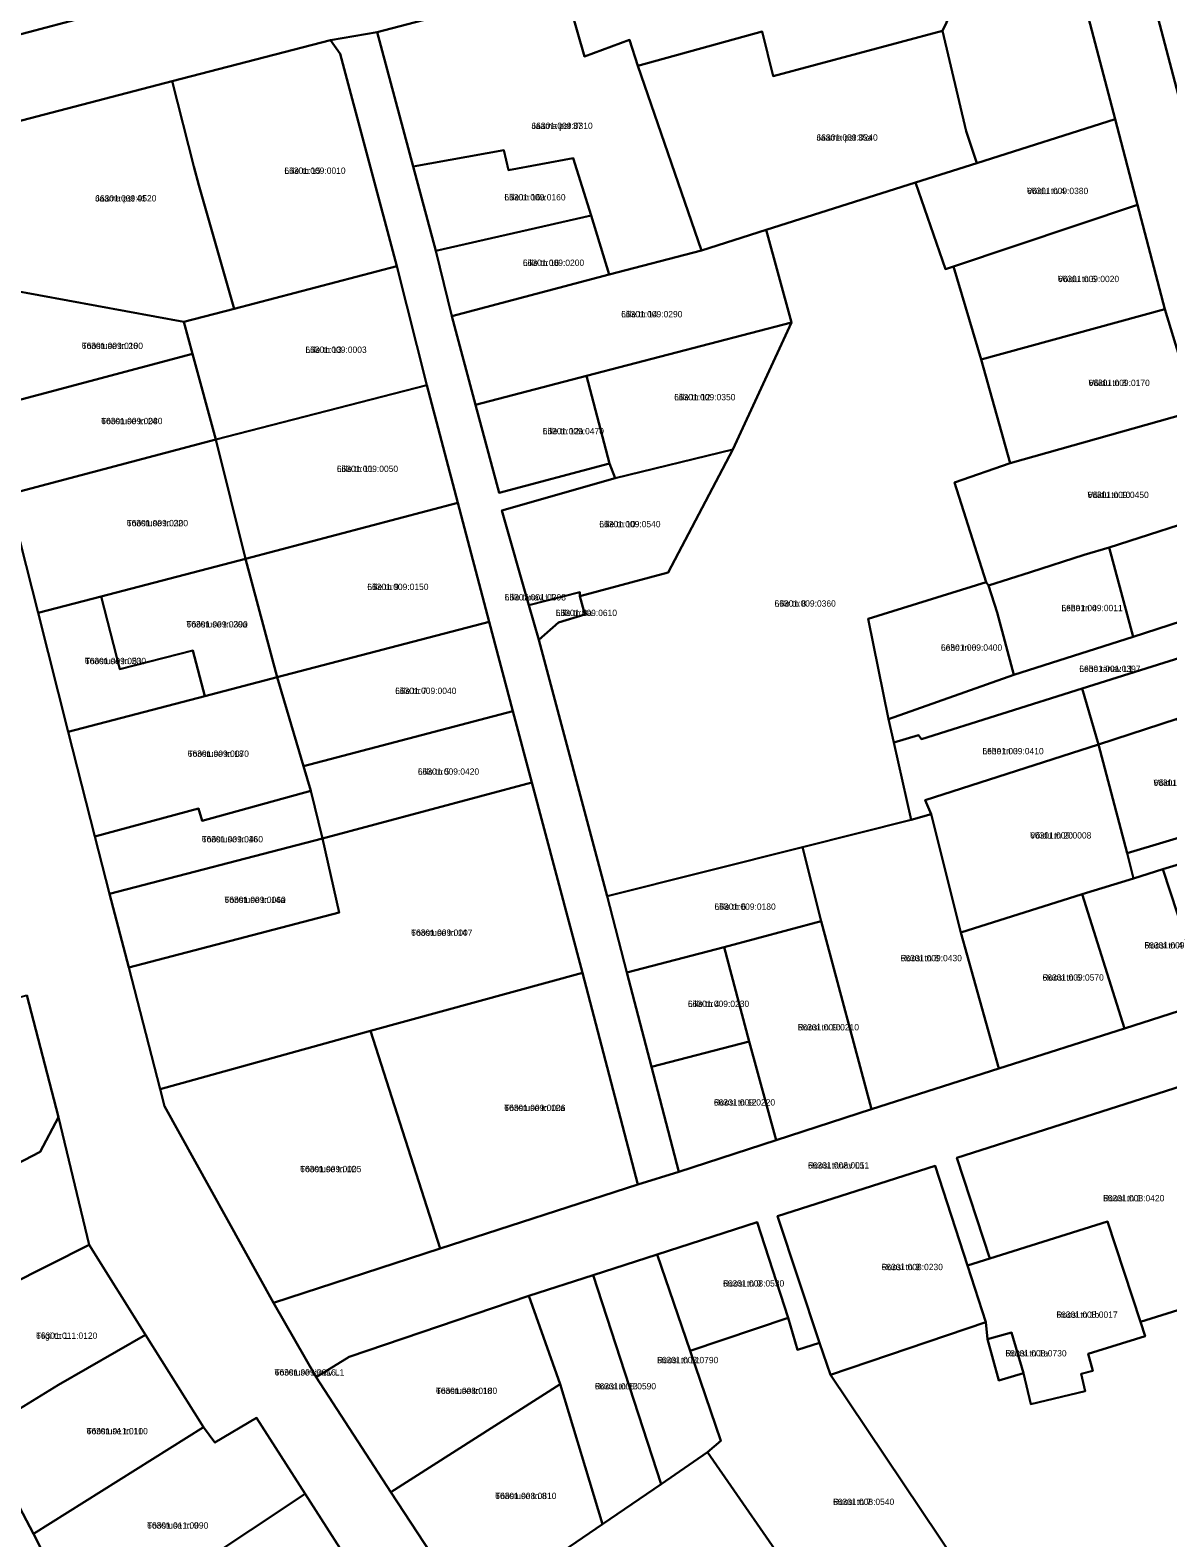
# Model space of a CAD drawing. Extents: x 632278 to 636344, y 6578401 to 6583362.
# Drawn here: x 633950.5 to 634219.9, y 6581799.1 to 6582156.3 of the extents above; entities that cross this region are included whole.
import ezdxf

# ---------------------------------------------------------------- set-up
doc = ezdxf.new("R2010")
doc.units = 0
for name, color, linetype in [('L_AADRESS', 7, 'Continuous'), ('PIIR', 7, 'Continuous'), ('TUNNUS', 7, 'Continuous')]:
    doc.layers.add(name, color=color, linetype=linetype)

msp = doc.modelspace()

# ---------------------------------------------------------------- linework, layer by layer
at = {"layer": 'PIIR'}
for points in [[(634226.55, 6582066.12), (634219.18, 6582090.2), (634212.69, 6582114.9), (634207.44, 6582135.18), (634193.9, 6582186.62), (634190.63, 6582199.04), (634184.13, 6582216.44), (634176.42, 6582237.01), (634195.12, 6582241.6), (634202.12, 6582218.6), (634206.36, 6582202), (634232.85, 6582101.14)], [(633468.65, 6582027.37), (633862.14, 6582132.61), (633966.83, 6582160.24), (634045.32, 6582180.97), (634095.76, 6582194.28), (634171.8, 6582213.35), (634184.13, 6582216.44), (634190.63, 6582199.04), (634142.64, 6582185.7), (634076.76, 6582167.38), (634032.67, 6582155.81), (634021.59, 6582153.91), (633984.06, 6582144.17), (633935.96, 6582131.59), (633888.34, 6582118.77), (633834.04, 6582103.56), (633748.13, 6582082.98), (633734.4, 6582070.6), (633580.94, 6582031.55)], [(633945.26, 6582046.29), (633952.38, 6582018.2), (633959.5, 6581990.06), (633965.77, 6581965.26), (633969.26, 6581951.67), (633973.83, 6581934.24), (633981.27, 6581905.36), (633982.32, 6581901.36), (634008.06, 6581854.81), (634018.24, 6581837.15), (634035.92, 6581809.94), (634054.81, 6581781.02)], [(634028.93, 6581788.71), (634015.57, 6581809.57), (634004.07, 6581827.51), (633994.24, 6581821.7), (633991.52, 6581825.32), (633989.41, 6581828.7), (633977.8, 6581847.2), (633964.41, 6581868.52), (633957.19, 6581898.78), (633949.71, 6581927.69)], [(634227.03, 6581907.36), (634169.9, 6581889.15), (634177.71, 6581865.32), (634172.48, 6581863.61), (634164.82, 6581887.26), (634127.43, 6581875.31), (634137.41, 6581845.3), (634132.2, 6581843.65), (634129.96, 6581851.23), (634122.65, 6581873.89), (634098.97, 6581866.23), (634083.84, 6581861.37), (634068.54, 6581856.46), (634026, 6581842.02), (634018.24, 6581837.15), (634008.06, 6581854.81), (634047.55, 6581867.62), (634094.4, 6581882.82), (634104.1, 6581885.8), (634127.15, 6581893.28), (634149.71, 6581900.62), (634179.88, 6581910.28), (634209.63, 6581919.77), (634229.1, 6581926.04)], [(634221.83, 6581772.31), (634198.51, 6581756.88), (634177.24, 6581788.29), (634174.47, 6581786.38), (634139.98, 6581837.74), (634176.83, 6581850.19), (634177.17, 6581846.17), (634179.86, 6581836.37), (634185.69, 6581838.09), (634187.47, 6581830.76), (634200.35, 6581833.87), (634199.37, 6581837.93), (634202.14, 6581838.66), (634201.07, 6581842.72), (634214.55, 6581846.87), (634213.43, 6581850.29), (634242.25, 6581859.26)]]:
    msp.add_lwpolyline(points, dxfattribs=at)
for points in [[(634206.36, 6582202), (634226.54, 6582207.17), (634227.13, 6582204.73), (634230.32, 6582192.25), (634233.16, 6582187.01), (634241.86, 6582153.04), (634252.38, 6582112.67), (634246.39, 6582104.55), (634232.85, 6582101.14)], [(634092.4, 6582154), (634081.72, 6582150.06), (634076.76, 6582167.38), (634142.64, 6582185.7), (634147.97, 6582167.04), (634164.74, 6582171.61), (634166.49, 6582164.58), (634171.19, 6582165.88), (634166.54, 6582156.12), (634126.47, 6582145.38), (634123.83, 6582155.98), (634094.42, 6582147.84)], [(634172.12, 6582132.37), (634166.54, 6582156.12), (634171.19, 6582165.88), (634178.5, 6582181.21), (634193.9, 6582186.62), (634207.44, 6582135.18), (634174.63, 6582124.76)], [(633961.3, 6582182.01), (633966.83, 6582160.24), (633862.14, 6582132.61), (633857.97, 6582155.11)], [(634062.61, 6582127.87), (634041.15, 6582123.97), (634032.67, 6582155.81), (634076.76, 6582167.38), (634081.72, 6582150.06), (634092.4, 6582154), (634094.42, 6582147.84), (634109.47, 6582104.07), (634087.56, 6582098.35), (634083.36, 6582112.35), (634079.03, 6582125.95), (634063.73, 6582123.14)], [(634160.12, 6582120.16), (634124.79, 6582108.93), (634109.47, 6582104.07), (634094.42, 6582147.84), (634123.83, 6582155.98), (634126.47, 6582145.38), (634166.54, 6582156.12), (634172.12, 6582132.37), (634174.63, 6582124.76)], [(633989.26, 6582123.94), (633984.06, 6582144.17), (634021.59, 6582153.91), (634023.89, 6582150.67), (634037.28, 6582100.34), (633998.8, 6582090.29), (633990.45, 6582119.57)], [(634023.89, 6582150.67), (634021.59, 6582153.91), (634032.67, 6582155.81), (634041.15, 6582123.97), (634046.52, 6582103.99), (634050.35, 6582088.48), (634055.94, 6582067.54), (634061.58, 6582046.69), (634087.71, 6582053.63), (634088.99, 6582050.13), (634062.17, 6582042.45), (634068.6, 6582020.08), (634070.94, 6582011.82), (634087.12, 6581951.1), (634091.78, 6581933.02), (634097.64, 6581910.69), (634104.1, 6581885.8), (634094.4, 6581882.82), (634081.28, 6581932.96), (634069.28, 6581978.08), (634064.77, 6581994.97), (634059.16, 6582016.14), (634051.79, 6582044.29), (634044.4, 6582072.2), (634037.28, 6582100.34)], [(633984.06, 6582144.17), (633989.26, 6582123.94), (633990.45, 6582119.57), (633998.8, 6582090.29), (633986.84, 6582087.18), (633945.69, 6582094.79), (633935.96, 6582131.59)], [(634167.23, 6582099.67), (634160.12, 6582120.16), (634174.63, 6582124.76), (634207.44, 6582135.18), (634212.69, 6582114.9), (634169.12, 6582100.29)], [(634046.52, 6582103.99), (634041.15, 6582123.97), (634062.61, 6582127.87), (634063.73, 6582123.14), (634079.03, 6582125.95), (634083.36, 6582112.35)], [(634087.12, 6581951.1), (634070.94, 6582011.82), (634075.62, 6582015.91), (634081.85, 6582017.88), (634080.67, 6582022.2), (634101.59, 6582027.77), (634116.86, 6582056.94), (634130.8, 6582087.03), (634124.79, 6582108.93), (634160.12, 6582120.16), (634167.23, 6582099.67), (634169.12, 6582100.29), (634175.72, 6582078.27), (634182.6, 6582053.72), (634169.36, 6582049.12), (634176.87, 6582025.47), (634148.91, 6582016.78), (634153.75, 6581993.05), (634154.99, 6581987.54), (634159.1, 6581969.18), (634133.38, 6581962.74)], [(634169.12, 6582100.29), (634212.69, 6582114.9), (634219.18, 6582090.2), (634175.72, 6582078.27)], [(634046.52, 6582103.99), (634083.36, 6582112.35), (634087.56, 6582098.35), (634050.35, 6582088.48)], [(634055.94, 6582067.54), (634050.35, 6582088.48), (634087.56, 6582098.35), (634109.47, 6582104.07), (634124.79, 6582108.93), (634130.8, 6582087.03), (634082.19, 6582074.37)], [(633986.84, 6582087.18), (633998.8, 6582090.29), (634037.28, 6582100.34), (634044.4, 6582072.2), (633994.43, 6582059.31), (633988.91, 6582079.57)], [(633934.01, 6582091.91), (633945.69, 6582094.79), (633986.84, 6582087.18), (633988.91, 6582079.57), (633940.23, 6582066.68)], [(634226.55, 6582066.12), (634182.6, 6582053.72), (634175.72, 6582078.27), (634219.18, 6582090.2)], [(634130.8, 6582087.03), (634116.86, 6582056.94), (634088.99, 6582050.13), (634087.71, 6582053.63), (634082.19, 6582074.37)], [(633945.26, 6582046.29), (633940.23, 6582066.68), (633988.91, 6582079.57), (633994.43, 6582059.31)], [(634055.94, 6582067.54), (634082.19, 6582074.37), (634087.71, 6582053.63), (634061.58, 6582046.69)], [(634044.4, 6582072.2), (634051.79, 6582044.29), (634001.45, 6582031.02), (633994.43, 6582059.31)], [(634187.38, 6582027.9), (634177.46, 6582024.73), (634176.87, 6582025.47), (634169.36, 6582049.12), (634182.6, 6582053.72), (634226.55, 6582066.12), (634231.98, 6582042.08), (634206, 6582033.74), (634200.11, 6582031.95)], [(633952.38, 6582018.2), (633945.26, 6582046.29), (633994.43, 6582059.31), (634001.45, 6582031.02), (633967.32, 6582022.1)], [(634080.63, 6582023.12), (634068.6, 6582020.08), (634062.17, 6582042.45), (634088.99, 6582050.13), (634116.86, 6582056.94), (634101.59, 6582027.77), (634080.67, 6582022.2)], [(634001.45, 6582031.02), (634051.79, 6582044.29), (634059.16, 6582016.14), (634008.94, 6582002.98)], [(634206, 6582033.74), (634231.98, 6582042.08), (634237.47, 6582020.95), (634211.69, 6582012.56)], [(634206, 6582033.74), (634211.69, 6582012.56), (634183.42, 6582003.53), (634179.48, 6582018.29), (634177.46, 6582024.73), (634187.38, 6582027.9), (634200.11, 6582031.95)], [(633988.99, 6582009.3), (633971.7, 6582004.89), (633967.32, 6582022.1), (634001.45, 6582031.02), (634008.94, 6582002.98), (633991.82, 6581998.51)], [(634148.91, 6582016.78), (634176.87, 6582025.47), (634177.46, 6582024.73), (634179.48, 6582018.29), (634183.42, 6582003.53), (634153.75, 6581993.05)], [(633952.38, 6582018.2), (633967.32, 6582022.1), (633971.7, 6582004.89), (633988.99, 6582009.3), (633991.82, 6581998.51), (633959.5, 6581990.06)], [(634068.6, 6582020.08), (634080.63, 6582023.12), (634080.67, 6582022.2), (634081.85, 6582017.88), (634075.62, 6582015.91), (634070.94, 6582011.82)], [(634153.75, 6581993.05), (634183.42, 6582003.53), (634211.69, 6582012.56), (634237.47, 6582020.95), (634239.59, 6582012.85), (634199.6, 6582000.28), (634161.6, 6581988.33), (634160.85, 6581989.22), (634154.99, 6581987.54)], [(634015.2, 6581981.9), (634008.94, 6582002.98), (634059.16, 6582016.14), (634064.77, 6581994.97)], [(634199.6, 6582000.28), (634239.59, 6582012.85), (634243.14, 6581999.8), (634222.13, 6581993.15), (634203.45, 6581987.01)], [(633959.5, 6581990.06), (633991.82, 6581998.51), (634008.94, 6582002.98), (634015.2, 6581981.9), (634016.95, 6581976.03), (633991.18, 6581968.96), (633990.31, 6581971.87), (633965.77, 6581965.26)], [(634163.82, 6581970.51), (634159.1, 6581969.18), (634154.99, 6581987.54), (634160.85, 6581989.22), (634161.6, 6581988.33), (634199.6, 6582000.28), (634203.45, 6581987.01), (634162.44, 6581973.83)], [(634016.95, 6581976.03), (634015.2, 6581981.9), (634064.77, 6581994.97), (634069.28, 6581978.08), (634019.67, 6581964.78)], [(634203.45, 6581987.01), (634222.13, 6581993.15), (634229.57, 6581967.08), (634210.24, 6581961.3)], [(634203.45, 6581987.01), (634210.24, 6581961.3), (634211.79, 6581955.34), (634199.64, 6581951.59), (634170.85, 6581942.52), (634163.82, 6581970.51), (634162.44, 6581973.83)], [(633973.83, 6581934.24), (634023.64, 6581947.26), (634019.67, 6581964.78), (634069.28, 6581978.08), (634081.28, 6581932.96), (634031.1, 6581919.25), (633981.27, 6581905.36)], [(633965.77, 6581965.26), (633990.31, 6581971.87), (633991.18, 6581968.96), (634016.95, 6581976.03), (634019.67, 6581964.78), (633969.26, 6581951.67)], [(634137.82, 6581945.16), (634133.38, 6581962.74), (634159.1, 6581969.18), (634163.82, 6581970.51), (634170.85, 6581942.52), (634179.88, 6581910.28), (634149.71, 6581900.62)], [(634210.24, 6581961.3), (634229.57, 6581967.08), (634250.38, 6581973.11), (634251.88, 6581967.45), (634218.71, 6581957.48), (634211.79, 6581955.34)], [(634229.1, 6581926.04), (634218.71, 6581957.48), (634251.88, 6581967.45), (634260.19, 6581936.06)], [(634019.67, 6581964.78), (634023.64, 6581947.26), (633973.83, 6581934.24), (633969.26, 6581951.67)], [(634137.82, 6581945.16), (634114.81, 6581939.04), (634091.78, 6581933.02), (634087.12, 6581951.1), (634133.38, 6581962.74)], [(634199.64, 6581951.59), (634211.79, 6581955.34), (634218.71, 6581957.48), (634229.1, 6581926.04), (634209.63, 6581919.77)], [(634170.85, 6581942.52), (634199.64, 6581951.59), (634209.63, 6581919.77), (634179.88, 6581910.28)], [(634120.74, 6581916.72), (634114.81, 6581939.04), (634137.82, 6581945.16), (634149.71, 6581900.62), (634127.15, 6581893.28)], [(634091.78, 6581933.02), (634114.81, 6581939.04), (634120.74, 6581916.72), (634097.64, 6581910.69)], [(634031.1, 6581919.25), (634081.28, 6581932.96), (634094.4, 6581882.82), (634047.55, 6581867.62)], [(633949.71, 6581927.69), (633957.19, 6581898.78), (633952.86, 6581890.56), (633928.96, 6581878.19), (633909.81, 6581916.52)], [(634031.1, 6581919.25), (634047.55, 6581867.62), (634008.06, 6581854.81), (633982.32, 6581901.36), (633981.27, 6581905.36)], [(634097.64, 6581910.69), (634120.74, 6581916.72), (634127.15, 6581893.28), (634104.1, 6581885.8)], [(634205.6, 6581874.01), (634177.71, 6581865.32), (634169.9, 6581889.15), (634227.03, 6581907.36), (634235.96, 6581878.51), (634242.25, 6581859.26), (634213.43, 6581850.29)], [(633746.05, 6581778.31), (633776.36, 6581792.95), (633778.15, 6581801.53), (633782.1, 6581812.81), (633788.02, 6581811.01), (633819.19, 6581824.49), (633851.9, 6581840.4), (633879.17, 6581853.47), (633905.37, 6581866.61), (633928.96, 6581878.19), (633952.86, 6581890.56), (633957.19, 6581898.78), (633964.41, 6581868.52), (633926.12, 6581849.23), (633822.63, 6581796.54), (633804.8, 6581787.45), (633771.82, 6581771.23), (633752.6, 6581762.41), (633751.15, 6581759.6)], [(634164.82, 6581887.26), (634172.48, 6581863.61), (634176.83, 6581850.19), (634139.98, 6581837.74), (634137.41, 6581845.3), (634127.43, 6581875.31)], [(634177.71, 6581865.32), (634205.6, 6581874.01), (634213.43, 6581850.29), (634214.55, 6581846.87), (634201.07, 6581842.72), (634202.14, 6581838.66), (634199.37, 6581837.93), (634200.35, 6581833.87), (634187.47, 6581830.76), (634185.69, 6581838.09), (634182.86, 6581847.72), (634177.17, 6581846.17), (634176.83, 6581850.19), (634172.48, 6581863.61)], [(634122.65, 6581873.89), (634129.96, 6581851.23), (634106.74, 6581843.39), (634098.97, 6581866.23)], [(633926.12, 6581849.23), (633964.41, 6581868.52), (633977.8, 6581847.2), (633957.17, 6581835.32), (633938.65, 6581823.98)], [(634098.97, 6581866.23), (634106.74, 6581843.39), (634114.03, 6581822.11), (634110.85, 6581819.43), (634099.87, 6581811.86), (634083.84, 6581861.37)], [(634076.01, 6581835.55), (634068.54, 6581856.46), (634083.84, 6581861.37), (634099.87, 6581811.86), (634086, 6581802.32)], [(634035.92, 6581809.94), (634018.24, 6581837.15), (634026, 6581842.02), (634068.54, 6581856.46), (634076.01, 6581835.55)], [(633822.63, 6581796.54), (633926.12, 6581849.23), (633938.65, 6581823.98), (633951.22, 6581800.08), (633963.84, 6581775.08), (633962.93, 6581774.45), (633946.33, 6581763.28), (633949.27, 6581756.32), (633921.58, 6581741.86), (633930.19, 6581700.67), (633902.7, 6581686.51)], [(634110.85, 6581819.43), (634114.03, 6581822.11), (634106.74, 6581843.39), (634129.96, 6581851.23), (634132.2, 6581843.65), (634137.41, 6581845.3), (634139.98, 6581837.74), (634174.47, 6581786.38), (634147.62, 6581767.25), (634133.47, 6581786.87), (634132.44, 6581788.31)], [(633989.41, 6581828.7), (633991.52, 6581825.32), (633951.22, 6581800.08), (633938.65, 6581823.98), (633957.17, 6581835.32), (633977.8, 6581847.2)], [(634182.86, 6581847.72), (634185.69, 6581838.09), (634179.86, 6581836.37), (634177.17, 6581846.17)], [(634035.92, 6581809.94), (634076.01, 6581835.55), (634086, 6581802.32), (634054.81, 6581781.02)], [(633951.22, 6581800.08), (633991.52, 6581825.32), (633994.24, 6581821.7), (634004.07, 6581827.51), (634015.57, 6581809.57), (633963.84, 6581775.08)], [(634076.7, 6581746), (634054.81, 6581781.02), (634086, 6581802.32), (634099.87, 6581811.86), (634110.85, 6581819.43), (634132.44, 6581788.31), (634104.62, 6581766.7)], [(633977.33, 6581753.35), (633962.93, 6581774.45), (633963.84, 6581775.08), (634015.57, 6581809.57), (634028.93, 6581788.71), (633995.89, 6581766.18)]]:
    msp.add_lwpolyline(points, close=True, dxfattribs=at)

# ---------------------------------------------------------------- texts
at = {"layer": 'L_AADRESS'}
for s, p in [('Jaama pst 37', (634069.18, 6582132.87)), ('Jaama pst 35a', (634136.7, 6582130.1)), ('Lille tn 15', (634010.67, 6582122.23)), ('Jaama pst 41', (633965.86, 6582115.68)), ('Lille tn 16a', (634062.77, 6582115.93)), ('Võidu tn 4', (634186.55, 6582117.43)), ('Lille tn 16', (634067.17, 6582100.42)), ('Võidu tn 6', (634193.87, 6582096.58)), ('Lille tn 14', (634090.44, 6582088.24)), ('Tööstuse tn 26', (633962.68, 6582080.74)), ('Lille tn 13', (634015.66, 6582079.82)), ('Võidu tn 8', (634201.13, 6582071.96)), ('Lille tn 12', (634102.99, 6582068.58)), ('Tööstuse tn 24', (633967.3, 6582062.93)), ('Lille tn 12a', (634071.85, 6582060.53)), ('Lille tn 11', (634023.1, 6582051.61)), ('Võidu tn 10', (634200.88, 6582045.43)), ('Tööstuse tn 22', (633973.35, 6582038.75)), ('Lille tn 10', (634085.26, 6582038.51)), ('Lille tn 9', (634030.31, 6582023.63)), ('Lille tänav L1', (634062.85, 6582021.17)), ('Lille tn 8', (634126.77, 6582019.7)), ('Lille tn 8a', (634074.95, 6582017.47)), ('Lehe tn 4', (634194.71, 6582018.63)), ('Tööstuse tn 20a', (633987.49, 6582014.77)), ('Lehe tn 6', (634166.17, 6582009.26)), ('Tööstuse tn 20', (633963.42, 6582006.08)), ('Lehe tänav L1', (634198.94, 6582004.24)), ('Lille tn 7', (634036.91, 6581999.02)), ('Tööstuse tn 18', (633987.77, 6581984.12)), ('Lehe tn 3', (634175.99, 6581984.73)), ('Lille tn 5', (634042.3, 6581979.88)), ('Võidu tn 18', (634216.51, 6581977.24)), ('Tööstuse tn 16', (633991.11, 6581963.85)), ('Võidu tn 20', (634187.29, 6581964.77)), ('Tööstuse tn 14a', (633996.48, 6581949.51)), ('Lille tn 6', (634112.54, 6581947.88)), ('Tööstuse tn 14', (634040.7, 6581941.72)), ('Roosi tn 4', (634214.37, 6581938.72)), ('Roosi tn 8', (634156.63, 6581935.7)), ('Roosi tn 6', (634190.24, 6581931.11)), ('Lille tn 4', (634106.25, 6581924.87)), ('Roosi tn 10', (634132.26, 6581919.31)), ('Roosi tn 12', (634112.39, 6581901.52)), ('Tööstuse tn 12a', (634062.75, 6581900.22)), ('Tööstuse tn 12', (634014.41, 6581885.73)), ('Roosi tänav L1', (634134.68, 6581886.6)), ('Roosi tn 1', (634204.57, 6581878.82)), ('Roosi tn 3', (634152.13, 6581862.52)), ('Roosi tn 9', (634114.56, 6581858.64)), ('Roosi tn 1b', (634193.51, 6581851.23)), ('Tiigi tn 1', (633951.87, 6581846.25)), ('Roosi tn 11', (634098.94, 6581840.48)), ('Roosi tn 1a', (634181.43, 6581842.08)), ('Tööstuse tänav L1', (634008.36, 6581837.56)), ('Tööstuse tn 10', (634046.57, 6581833.2)), ('Roosi tn 13', (634084.2, 6581834.27)), ('Tööstuse tn 11', (633963.83, 6581823.64)), ('Tööstuse tn 8', (634060.6, 6581808.29)), ('Roosi tn 7', (634140.61, 6581806.89)), ('Tööstuse tn 9', (633978.16, 6581801.29))]:
    msp.add_text(s, height=1.5, dxfattribs=at).set_placement(p)
at = {"layer": 'TUNNUS'}
for s, p in [('66301:009:0310', (634069.18, 6582132.87)), ('66301:009:0240', (634136.7, 6582130.1)), ('66301:009:0010', (634010.67, 6582122.23)), ('66301:009:0520', (633965.86, 6582115.68)), ('66301:009:0160', (634062.77, 6582115.93)), ('66301:009:0380', (634186.55, 6582117.43)), ('66301:009:0200', (634067.17, 6582100.42)), ('66301:009:0020', (634193.87, 6582096.58)), ('66301:009:0290', (634090.44, 6582088.24)), ('66301:009:0100', (633962.68, 6582080.74)), ('66301:009:0003', (634015.66, 6582079.82)), ('66301:009:0170', (634201.13, 6582071.96)), ('66301:009:0350', (634102.99, 6582068.58)), ('66301:009:0080', (633967.3, 6582062.93)), ('66301:009:0470', (634071.85, 6582060.53)), ('66301:009:0050', (634023.1, 6582051.61)), ('66301:009:0450', (634200.88, 6582045.43)), ('66301:009:0300', (633973.35, 6582038.75)), ('66301:009:0540', (634085.26, 6582038.51)), ('66301:009:0150', (634030.31, 6582023.63)), ('66301:001:0398', (634062.85, 6582021.17)), ('66301:009:0360', (634126.77, 6582019.7)), ('66301:009:0610', (634074.95, 6582017.47)), ('66301:009:0011', (634194.71, 6582018.63)), ('66301:009:0390', (633987.49, 6582014.77)), ('66301:009:0400', (634166.17, 6582009.26)), ('66301:009:0530', (633963.42, 6582006.08)), ('66301:001:0397', (634198.94, 6582004.24)), ('66301:009:0040', (634036.91, 6581999.02)), ('66301:009:0070', (633987.77, 6581984.12)), ('66301:009:0410', (634175.99, 6581984.73)), ('66301:009:0420', (634042.3, 6581979.88)), ('66301:009:0620', (634216.51, 6581977.24)), ('66301:009:0460', (633991.11, 6581963.85)), ('66301:009:0008', (634187.29, 6581964.77)), ('66301:009:0060', (633996.48, 6581949.51)), ('66301:009:0180', (634112.54, 6581947.88)), ('66301:009:0007', (634040.7, 6581941.72)), ('66301:009:0490', (634214.37, 6581938.72)), ('66301:009:0430', (634156.63, 6581935.7)), ('66301:009:0570', (634190.24, 6581931.11)), ('66301:009:0230', (634106.25, 6581924.87)), ('66301:009:0210', (634132.26, 6581919.31)), ('66301:009:0220', (634112.39, 6581901.52)), ('66301:009:0006', (634062.75, 6581900.22)), ('66301:009:0005', (634014.41, 6581885.73)), ('66301:008:0051', (634134.68, 6581886.6)), ('66301:008:0420', (634204.57, 6581878.82)), ('66301:008:0230', (634152.13, 6581862.52)), ('66301:008:0530', (634114.56, 6581858.64)), ('66301:008:0017', (634193.51, 6581851.23)), ('66301:011:0120', (633951.87, 6581846.25)), ('66301:008:0790', (634098.94, 6581840.48)), ('66301:008:0730', (634181.43, 6581842.08)), ('66301:009:0016', (634008.36, 6581837.56)), ('66301:008:0180', (634046.57, 6581833.2)), ('66301:008:0590', (634084.2, 6581834.27)), ('66301:011:0100', (633963.83, 6581823.64)), ('66301:008:0810', (634060.6, 6581808.29)), ('66301:008:0540', (634140.61, 6581806.89)), ('66301:011:0090', (633978.16, 6581801.29))]:
    msp.add_text(s, height=1.5, dxfattribs=at).set_placement(p)

doc.saveas('drawing.dxf')
